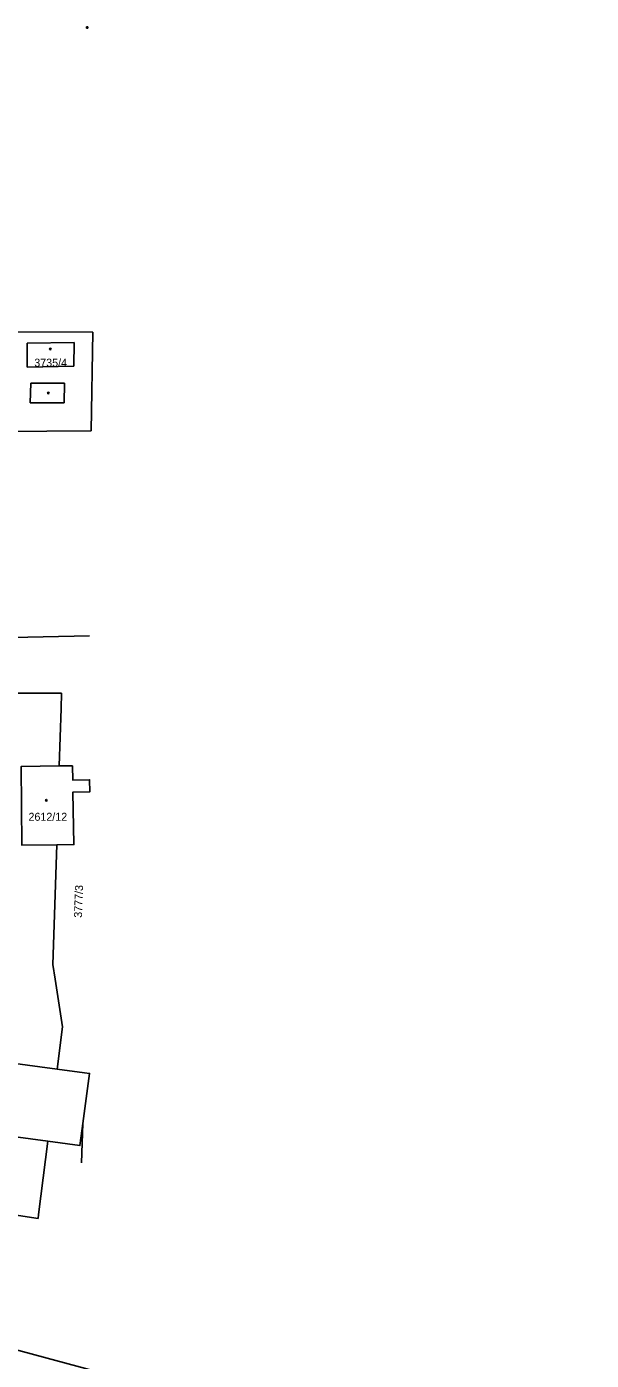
# Model space of a CAD drawing. Extents: x -527335 to -526256, y -1079142 to -1077809.
# Drawn here: x -526375.8 to -526255.8, y -1078442 to -1078158.7 of the extents above; entities that cross this region are included whole.
import ezdxf

# ---------------------------------------------------------------- set-up
doc = ezdxf.new("R2010")
doc.units = 0
for name, color, linetype in [('Vrstva 1', 7, 'Continuous'), ('Vrstva 2', 7, 'Continuous'), ('Vrstva 4', 7, 'Continuous'), ('Vrstva 5', 7, 'Continuous')]:
    doc.layers.add(name, color=color, linetype=linetype)

msp = doc.modelspace()

# ---------------------------------------------------------------- linework, layer by layer
at = {"layer": 'Vrstva 1'}
for p, q in [((-526361.75, -1078223.62), (-526378.34, -1078223.51)), ((-526363.48, -1078380.94), (-526369.31, -1078380.15)), ((-526364.12, -1078400.1), (-526363.84, -1078391.74))]:
    msp.add_line(p, q, dxfattribs=at)
for points in [[(-526380.88, -1078244.69), (-526362.1, -1078244.53), (-526361.75, -1078223.62)], [(-526368.35, -1078300.3), (-526392.03, -1078300.3), (-526433.75, -1078302.47), (-526450.54, -1078303.34), (-526493.09, -1078313.52), (-526500.68, -1078315.9), (-526538.39, -1078327.72)], [(-526368.84, -1078315.76), (-526368.46, -1078303.54), (-526368.35, -1078300.3)], [(-526369.38, -1078332.51), (-526376.77, -1078332.6), (-526376.93, -1078315.85), (-526368.84, -1078315.76)], [(-526369.38, -1078332.51), (-526365.74, -1078332.47), (-526365.95, -1078321.31), (-526362.36, -1078321.26), (-526362.41, -1078318.7), (-526365.99, -1078318.77), (-526366.04, -1078315.73), (-526368.84, -1078315.76)], [(-526369.31, -1078380.15), (-526368.16, -1078371.16), (-526369.73, -1078361.06), (-526370.19, -1078357.9), (-526369.38, -1078332.51)], [(-526371.27, -1078395.48), (-526431.8, -1078387.34), (-526429.78, -1078372), (-526369.31, -1078380.15)], [(-526363.84, -1078391.74), (-526362.41, -1078381.08), (-526363.48, -1078380.94)], [(-526371.27, -1078395.48), (-526364.47, -1078396.4), (-526363.84, -1078391.74)], [(-526373.3, -1078411.92), (-526373.26, -1078411.04), (-526371.27, -1078395.48)], [(-526564.52, -1078422.23), (-526553.55, -1078417.76), (-526496.54, -1078407.33), (-526464.62, -1078404.48), (-526434.2, -1078404.33), (-526403.84, -1078407.24), (-526373.3, -1078411.92)], [(-526255.84, -1078485.88), (-526269.44, -1078477.46), (-526275.29, -1078479.08), (-526290.24, -1078467.75), (-526298.87, -1078468), (-526349.1, -1078447.58), (-526381.09, -1078438.93), (-526412.01, -1078434.75), (-526470.91, -1078435.12), (-526515.41, -1078439.88), (-526541.88, -1078447.21), (-526576.22, -1078459.13), (-526589.61, -1078459.9), (-526628.8, -1078481.46), (-526632.26, -1078483.8)]]:
    msp.add_lwpolyline(points, dxfattribs=at)
at = {"layer": 'Vrstva 4'}
for p, q in [((-526375.68, -1078231.02), (-526375.67, -1078225.95)), ((-526375.67, -1078225.95), (-526365.69, -1078225.81)), ((-526365.69, -1078225.81), (-526365.72, -1078230.81)), ((-526365.72, -1078230.81), (-526375.68, -1078231.02)), ((-526374.99, -1078238.59), (-526374.91, -1078234.4)), ((-526374.91, -1078234.4), (-526367.72, -1078234.43)), ((-526367.72, -1078234.43), (-526367.81, -1078238.6)), ((-526367.81, -1078238.6), (-526374.99, -1078238.59)), ((-526362.42, -1078288.09), (-526395.78, -1078288.82))]:
    msp.add_line(p, q, dxfattribs=at)
at = {"layer": 'Vrstva 5'}
for centre in [(-526362.92, -1078158.86), (-526370.75, -1078227.18), (-526371.16, -1078236.53), (-526371.59, -1078323.04)]:
    msp.add_circle(centre, 0.175, dxfattribs=at)

# ---------------------------------------------------------------- texts
at = {"layer": 'Vrstva 2'}
for s, p in [('3735/4', (-526374.15, -1078230.92)), ('2612/12', (-526375.38, -1078327.4))]:
    msp.add_text(s, height=1.7, dxfattribs=at).set_placement(p)
msp.add_text('3777/3', height=1.7, rotation=88, dxfattribs=at).set_placement((-526364.03, -1078348.03))

doc.saveas('drawing.dxf')
